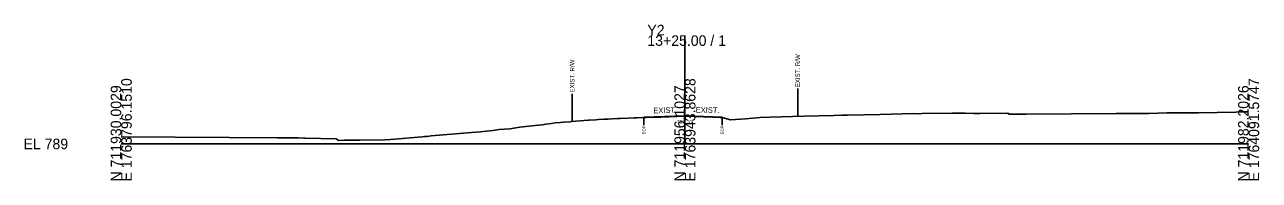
# Model space of a CAD drawing. Extents: x -26 to 1764011, y -10 to 712381.
# Drawn here: x 1274.3 to 1602.8, y -9.7 to 31.7 of the extents above; entities that cross this region are included whole.
import ezdxf

# ---------------------------------------------------------------- set-up
doc = ezdxf.new("R2010")
doc.units = 0
for name, color, linetype in [('Exist Cross Section Cell', 7, 'Continuous'), ('Exist XS Center Line Elevation Label', 7, 'Continuous'), ('Exist XS Ground Line', 7, 'Continuous'), ('Old_Level_10', 7, 'Continuous'), ('Prop CMT Pvmt Course 1', 7, 'Continuous'), ('Prop XS SE Text', 7, 'Continuous')]:
    doc.layers.add(name, color=color, linetype=linetype)

msp = doc.modelspace()

# ---------------------------------------------------------------- linework, layer by layer
at = {"layer": 'Exist Cross Section Cell'}
for p, q in [((1450, 0), (1450, 28.91)), ((1300, 0), (1450, 0)), ((1450, 0), (1600, 0))]:
    msp.add_line(p, q, dxfattribs=at)
at = {"layer": 'Exist XS Ground Line'}
msp.add_lwpolyline([(1300, 1.86), (1328.69, 1.7), (1341.47, 1.62), (1344.04, 1.61), (1344.39, 1.6), (1347.08, 1.58), (1348.57, 1.57), (1348.95, 1.55), (1357.21, 1.38), (1357.77, 0.88), (1359.45, 0.97), (1363.51, 1.04), (1370.2, 1.08), (1371.62, 1.16), (1380.06, 1.91), (1380.7, 1.95), (1381.43, 2.01), (1382.47, 2.12), (1393.16, 3.05), (1395.51, 3.24), (1398.88, 3.59), (1400.55, 3.82), (1403.39, 4.05), (1406.06, 4.44), (1410.12, 4.86), (1412.07, 5.06), (1412.96, 5.22), (1414.51, 5.47), (1415.51, 5.57), (1416.88, 5.68), (1417.67, 5.76), (1419.42, 5.92), (1419.82, 5.96), (1422.11, 6.14), (1424.14, 6.28), (1424.5, 6.31), (1426.3, 6.42), (1427.04, 6.47), (1428.45, 6.55), (1429.58, 6.61), (1430.61, 6.67), (1432.11, 6.76), (1432.77, 6.78), (1434.93, 6.85), (1436.48, 6.93), (1437.19, 6.97), (1439.24, 7.01), (1439.73, 7.03), (1441.4, 7.1), (1442.27, 7.12), (1443.56, 7.16), (1444.81, 7.2), (1445.71, 7.23), (1447.35, 7.28), (1447.87, 7.3), (1450, 7.37), (1450.74, 7.35), (1452.42, 7.31), (1454.34, 7.27), (1454.96, 7.26), (1456.5, 7.22), (1457.5, 7.19), (1459.39, 7.07), (1459.93, 7.03), (1462.09, 6.37), (1466.12, 6.7), (1470, 7.06), (1472.64, 7.16), (1481.6, 7.42), (1489.64, 7.59), (1491.76, 7.62), (1493.24, 7.69), (1501.91, 7.8), (1510.76, 8.06), (1512.03, 8.05), (1513.16, 8.07), (1521.22, 8.18), (1522.71, 8.18), (1524.57, 8.16), (1526.91, 8.13), (1528.52, 8.1), (1535.91, 8.21), (1536.32, 7.96), (1540.8, 7.89), (1564.78, 8.1), (1567.5, 8.1), (1570.08, 8.1), (1573.45, 8.12), (1578.25, 8.27), (1586.65, 8.31), (1596.57, 8.49), (1597.82, 8.5), (1599.12, 8.51), (1600, 8.5)], dxfattribs=at)
at = {"layer": 'Old_Level_10'}
for p, q in [((1420, 13.37), (1420, 5.97)), ((1480, 14.78), (1480, 7.38)), ((1439.09, 7.01), (1439.09, 4.96)), ((1459.93, 7.03), (1459.93, 4.98))]:
    msp.add_line(p, q, dxfattribs=at)
at = {"layer": 'Prop CMT Pvmt Course 1'}
for points in [[(1450, 7.5), (1439.08, 7.13)], [(1450, 7.37), (1439.09, 7.01)], [(1450, 7.5), (1459.93, 7.16)], [(1450, 7.37), (1459.93, 7.03)]]:
    msp.add_lwpolyline(points, dxfattribs=at)

# ---------------------------------------------------------------- texts
at = {"layer": 'Exist Cross Section Cell'}
for s, p in [('Y2', (1440, 28.91)), ('13+25.00 / 1', (1440, 26.11)), ('EL 789', (1274, -1.4))]:
    msp.add_text(s, height=2.8, dxfattribs=at).set_placement(p)
for s, p in [('E 1763796.1510', (1302.8, -10)), ('E 1763943.8628', (1452.8, -10)), ('E 1764091.5747', (1602.8, -10)), ('N 711930.0029', (1300, -10)), ('N 711956.1027', (1450, -10)), ('N 711982.2026', (1600, -10))]:
    msp.add_text(s, height=2.8, rotation=90, dxfattribs=at).set_placement(p)
at = {"layer": 'Exist XS Center Line Elevation Label'}
msp.add_text('796.37', height=1, dxfattribs=at).set_placement((1447.85, 5.37))
at = {"layer": 'Old_Level_10'}
for s, height, p in [('EXIST. R/W', 1.181, (1480.59, 15.08)), ('EXIST. R/W', 1.181, (1420.59, 13.67)), ('EOP', 0.787, (1439.48, 2.56)), ('EOP', 0.787, (1460.32, 2.58))]:
    msp.add_text(s, height=height, rotation=90, dxfattribs=at).set_placement(p)
at = {"layer": 'Prop XS SE Text'}
for rotation, p in [(1.6611, (1441.6, 8.13)), (358.9688, (1452.85, 8.32))]:
    msp.add_text('EXIST.', height=1.5, rotation=rotation, dxfattribs=at).set_placement(p)

doc.saveas('drawing.dxf')
